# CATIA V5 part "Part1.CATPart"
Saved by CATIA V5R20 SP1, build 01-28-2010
Part number: Piece3
Bounding box of the stored display mesh (mm): x 18.735 to 60.295, y 116.378 to 193.749, z -267.497 to 14.986
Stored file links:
  C:\Users\RENARD Simon\Documents\Cours IFMA\2ème année\IAO\Part1.CATPart
  C:\Users\RENARD Simon\Documents\Cours IFMA\2ème année\IAO\Trainattero.CATProduct
  C:\Users\RENARD Simon\Documents\Cours IFMA\2ème année\IAO\Sqpiece3.CATPart
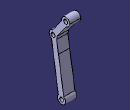
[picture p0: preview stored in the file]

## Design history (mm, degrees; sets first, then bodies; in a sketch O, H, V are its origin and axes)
Set1
  Plane1: linked copy from another document
  Line1 to Line3: linked copy from another document
Body1 (main body)
  Sketch1 on Plane1, origin (36.3239, -0.7439, 0), H (0.0205, 0.9998, 0), V (0, 0, 1)
    arc A1 centre (163.5883, -252.4969) radius 15 from (151.9884, -242.9868) to (171.7507, -239.9121) ccw
    point P1 (163.5883, -252.4969)
    arc A2 centre (132.5551, -65.0484) radius 15 from (130.9323, -50.1364) to (126.4349, -78.743) ccw
    point P2 (132.5551, -65.0484)
    arc A3 centre (179.1245, 0) radius 15 from (194.1245, 0) to (164.4852, -3.2696) ccw
    point P3 (179.1245, 0)
    reference projected point E1 (163.5883, -252.4969) from Line1
    reference projected point E2 (132.5551, -65.0484) from Line2
    reference projected point E3 (179.1245, 0) from Line3
    line L1 (126.4349, -78.743) -> (151.9884, -242.9868)
    point P6 (145.6758, -72.3179)
    line L2 (145.6758, -72.3179) -> (152.4644, -115.951)
    point P8 (180.7473, -14.912)
    line L3 (180.7473, -14.912) -> (147.1944, -61.7788)
    line L4 (164.4852, -3.2696) -> (130.9323, -50.1364)
    reference projected point E4 (163.5883, -252.4969) from Line1
    reference projected point E5 (179.1245, 0) from Line3
    reference projected point E6 (132.5551, -65.0484) from Line2
    arc A4 centre (179.1245, 0) radius 15 from (180.7473, -14.912) to (194.1245, 0) ccw
    point P12 (194.1245, 0)
    point P13 (194.1245, 0)
    line L5 (152.4644, -115.951) -> (171.7507, -239.9121)
    arc A5 centre (132.5551, -65.0484) radius 15 from (145.6758, -72.3179) to (147.1944, -61.7788) ccw
    radius A1 = 15
    radius A2 = 15
    radius A3 = 15
    distance L2 L1 = 20
    distance L2 E4 = 10
    distance L3 E5 = 10
    distance L4 L3 = 20
    distance E6 L3 = 10
    coincidence: P3 H, P1 E1, P2 E2, P3 E3, P6 A2, P8 A3, A3 A4, L2 L5, A2 A5, P12 P13
    parallelism: L2 L1
  Pad1: profile Sketch1, direction (0.9998, -0.0205, 0), length 20, mirrored extent
  Sketch2 on start face of Pad1, origin (16.3281, -0.3344, 0), H (-0.0205, -0.9998, 0), V (0, 0, 1)
    circle A1 centre (-179.1245, 0) radius 7.5
    point P1 (-179.1245, 0)
    point P2 (-186.6245, 0)
    circle A2 centre (-132.5551, -65.0484) radius 7.5
    point P3 (-132.5551, -65.0484)
    circle A3 centre (-163.5883, -252.4969) radius 7.5
    point P4 (-163.5883, -252.4969)
    reference projected point E1 (-163.5883, -252.4969) from Line1
    reference projected point E2 (-132.5551, -65.0484) from Line2
    reference projected point E3 (-179.1245, 0) from Line3
    radius A3 = 7.5
    radius A1 = 7.5
    radius A2 = 7.5
    coincidence: A1 P2, P2 H, P4 E1, P3 E2, P1 E3
  Pocket1: profile Sketch2, direction (0.9998, -0.0205, 0), length 40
